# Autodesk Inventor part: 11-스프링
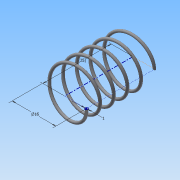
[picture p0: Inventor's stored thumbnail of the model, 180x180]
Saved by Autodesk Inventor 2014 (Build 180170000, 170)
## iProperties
Created: 2015-06
Part Number: 11-스프링
Material: 강철, 연강
Document SubType Name: Modeling
Designer: Administrator
Density: 7.86 g/cm^3
Appearance: 강철
Mass: 1.53535 g
Surface Area: 7.89038 cm^2
Volume: 0.195337 cm^3
Author: Administrator
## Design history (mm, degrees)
sketch "스케치1"
  geometry: L1 (0, 0)-(8, 0); L2 (8, 0)-(8, 21.5); L3 (8, 21.5)-(0, 21.5); L4 (0, 21.5)-(0, 0); C1 r 0.5 at (8, 0)
  constraints: 8 end point, 2 parallel, 1 centre point, 1 coincident, 1 horizontal, 1 perpendicular
  dimensions: "d0" = 21.5 distance of L3.end L1.start (derived); "d1" = 16 diameter of L1.end L4; "d2" = 1 diameter of C1
feature "코일1" sketch "스케치1" pitch "d3" = 10; turns "d5" = 5; dims "d4" = 21.5 (= d0), "d6" = 0, angle "d7" = 90 deg, angle "d8" = 90 deg, "d9" = 0, "d10" = 0
sketch "스케치2"
  geometry: L1 (15.5, -10)-(-15.5, -10); L2 (-15.5, -10)-(-15.5, 0); L3 (-15.5, 0)-(15.5, 0); L4 (15.5, 0)-(15.5, -10); L5 (-20, 31.5)-(20, 31.5); L6 (20, 31.5)-(20, 21.5); L7 (20, 21.5)-(-20, 21.5); L8 (-20, 21.5)-(-20, 31.5); 3 further points
  constraints: 16 end point, 4 parallel, 2 horizontal, 2 midpoint, 2 perpendicular, 1 coincident, 1 vertical alignment
  dimensions: "d11" = 10 distance of L3.end L1.start; "d12" = 31 distance of L1.start L1.end; "d13" = 21.5 distance between parallel lines of L3 L7 (= d0); "d14" = 10 distance of L5.end L6.end; "d15" = 40 distance of L5.start L5.end
extrude "돌출1" cut sketch "스케치2" stored distance "d16" = 0; taper "d17" = 0 deg
node "솔리드1"
